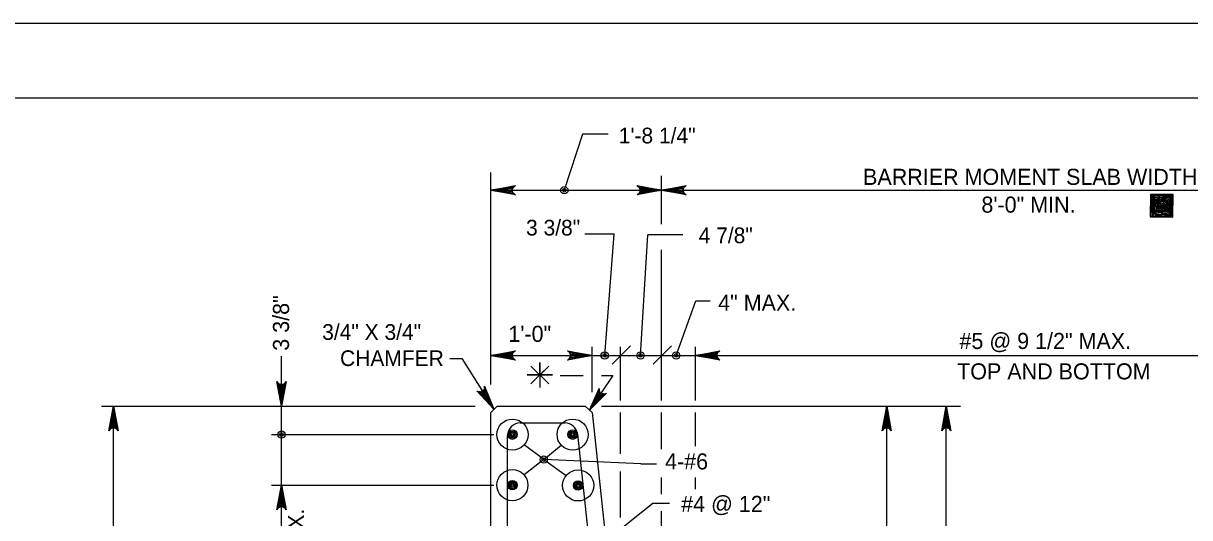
# Model space of a CAD drawing. Extents: x 638167 to 640248, y 296544 to 298920.
# Drawn here: x 639469.7 to 639703.7, y 298821.3 to 298920.5 of the extents above; entities that cross this region are included whole.
import ezdxf

# ---------------------------------------------------------------- set-up
doc = ezdxf.new("R2010")
doc.units = 0
for name, color, linetype in [('1', 7, 'Continuous'), ('50', 7, 'Continuous'), ('57', 7, 'Continuous'), ('PLT-BNDY', 7, 'Continuous')]:
    doc.layers.add(name, color=color, linetype=linetype)

# ---------------------------------------------------------------- blocks, each defined once
blk = doc.blocks.new('DIMDOT')
at = {"layer": '57'}
for radius in [2, 1]:
    blk.add_circle((0, 0), radius, dxfattribs=at)
blk = doc.blocks.new('BAR')
at = {"layer": '50'}
for radius in [2, 1.5, 1, 0.5]:
    blk.add_circle((0, 0), radius, dxfattribs=at)

msp = doc.modelspace()

# ---------------------------------------------------------------- linework, layer by layer
at = {"layer": '1'}
for p, q in [((639832.78, 298905.48), (639046.78, 298905.48)), ((639581.86, 298898.27), (639578.24, 298887)), ((639587.05, 298898.27), (639581.86, 298898.27)), ((639563.48, 298848.05), (639563.48, 298890.55)), ((639597.77, 298880.22), (639597.77, 298889.87)), ((639563.48, 298887), (639760.33, 298887)), ((639698.12, 298883.9), (639698.12, 298883.9)), ((639588.24, 298878.22), (639582.37, 298878.22)), ((639586.34, 298853.88), (639588.24, 298878.22)), ((639593.53, 298853.88), (639595, 298878.06)), ((639602.02, 298878.06), (639595, 298878.06)), ((639597.77, 298844.81), (639597.77, 298875.03)), ((639600.67, 298853.88), (639604.65, 298864.8)), ((639604.65, 298864.8), (639607.48, 298864.8)), ((639583.8, 298846.51), (639583.8, 298855.62)), ((639591.5, 298855.81), (639587.81, 298852.12)), ((639589.51, 298844.81), (639589.51, 298855.62)), ((639599.76, 298855.81), (639596.07, 298852.12)), ((639604.54, 298844.81), (639604.54, 298855.62)), ((639521.48, 298810.67), (639521.48, 298853.73)), ((639555.28, 298853.25), (639557.66, 298853.25)), ((639557.66, 298853.25), (639564.11, 298843.08)), ((639563.48, 298853.88), (639769.86, 298853.88)), ((639573.32, 298849.96), (639573.32, 298849.96)), ((639485.37, 298843.72), (639560.34, 298843.72)), ((639487.76, 298772.6), (639487.76, 298843.72)), ((639563.48, 298842.45), (639564.75, 298843.72)), ((639564.75, 298843.72), (639582.39, 298843.72)), ((639582.39, 298843.72), (639583.8, 298842.45)), ((639585.67, 298843.72), (639657.76, 298843.72)), ((639642.93, 298756.11), (639642.93, 298843.72)), ((639654.9, 298772.6), (639654.9, 298843.72)), ((639563.48, 298777.25), (639563.48, 298842.45)), ((639583.8, 298842.45), (639589.05, 298793.78)), ((639589.51, 298834.18), (639589.51, 298842.45)), ((639597.77, 298835.11), (639597.77, 298842.45)), ((639604.54, 298835.67), (639604.54, 298842.45)), ((639569.4, 298840.33), (639578.34, 298840.33)), ((639580.86, 298838.06), (639586.9, 298782.18)), ((639519.46, 298838), (639564.07, 298838)), ((639566.86, 298796.64), (639566.86, 298837.79)), ((639574.13, 298833), (639570.2, 298835.97)), ((639574.15, 298833.02), (639577.63, 298835.87)), ((639574.13, 298833), (639570.17, 298829.91)), ((639574.13, 298833), (639578.61, 298829.79)), ((639593.58, 298832.17), (639574.15, 298833.02)), ((639593.58, 298832.17), (639596.75, 298832.17)), ((639589.51, 298821.37), (639589.51, 298830.61)), ((639597.77, 298826.08), (639597.77, 298829.41)), ((639604.54, 298827.07), (639604.54, 298829.41)), ((639519.46, 298827.84), (639564.07, 298827.84)), ((639596.1, 298824.28), (639583.45, 298814.15)), ((639596.1, 298824.28), (639599.36, 298824.28)), ((639597.77, 298808.29), (639597.77, 298822.62))]:
    msp.add_line(p, q, dxfattribs=at)
for points in [[(639563.48, 298887), (639568.41, 298887.93), (639568.22, 298887.79), (639568.03, 298887.66), (639567.93, 298887.5), (639567.83, 298887.33), (639567.8, 298887.17), (639567.78, 298887), (639567.8, 298886.84), (639567.83, 298886.67), (639567.93, 298886.51), (639568.03, 298886.34), (639568.22, 298886.21), (639568.41, 298886.08), (639563.48, 298887), (639568.22, 298886.21), (639568.03, 298886.34), (639563.48, 298887), (639567.93, 298886.51), (639567.83, 298886.67), (639563.48, 298887), (639567.8, 298886.84), (639567.78, 298887), (639563.48, 298887), (639567.8, 298887.17), (639567.83, 298887.33), (639563.48, 298887), (639567.93, 298887.5), (639568.03, 298887.66), (639563.48, 298887), (639568.22, 298887.79)], [(639597.77, 298887), (639592.83, 298886.08), (639593.02, 298886.21), (639593.21, 298886.34), (639593.31, 298886.51), (639593.41, 298886.67), (639593.44, 298886.84), (639593.47, 298887), (639593.44, 298887.17), (639593.41, 298887.33), (639593.31, 298887.5), (639593.21, 298887.66), (639593.02, 298887.79), (639592.83, 298887.93), (639597.77, 298887), (639593.02, 298887.79), (639593.21, 298887.66), (639597.77, 298887), (639593.31, 298887.5), (639593.41, 298887.33), (639597.77, 298887), (639593.44, 298887.17), (639593.47, 298887), (639597.77, 298887), (639593.44, 298886.84), (639593.41, 298886.67), (639597.77, 298887), (639593.31, 298886.51), (639593.21, 298886.34), (639597.77, 298887), (639593.02, 298886.21)], [(639597.77, 298887), (639602.7, 298887.93), (639602.51, 298887.79), (639602.32, 298887.66), (639602.22, 298887.5), (639602.12, 298887.33), (639602.09, 298887.17), (639602.07, 298887), (639602.09, 298886.84), (639602.12, 298886.67), (639602.22, 298886.51), (639602.32, 298886.34), (639602.51, 298886.21), (639602.7, 298886.08), (639597.77, 298887), (639602.51, 298886.21), (639602.32, 298886.34), (639597.77, 298887), (639602.22, 298886.51), (639602.12, 298886.67), (639597.77, 298887), (639602.09, 298886.84), (639602.07, 298887), (639597.77, 298887), (639602.09, 298887.17), (639602.12, 298887.33), (639597.77, 298887), (639602.22, 298887.5), (639602.32, 298887.66), (639597.77, 298887), (639602.51, 298887.79)], [(639695.88, 298886.18), (639695.83, 298881.66), (639700.36, 298881.61), (639700.41, 298886.13), (639695.88, 298886.18), (639696.14, 298881.95), (639700.08, 298881.78), (639700.19, 298885.91), (639696.21, 298885.86), (639696.39, 298882.25), (639699.84, 298882.09), (639699.94, 298885.54), (639696.45, 298885.55), (639696.67, 298882.53), (639699.63, 298882.43), (639699.63, 298885.3), (639696.79, 298885.15), (639697.01, 298882.8), (639699.29, 298882.71), (639699.31, 298884.99), (639697.09, 298884.83), (639697.32, 298883.17), (639698.95, 298882.99), (639699.06, 298884.63), (639697.34, 298884.71), (639697.48, 298883.44), (639698.71, 298883.37), (639698.72, 298884.23), (639697.86, 298884.42), (639697.79, 298883.69), (639698.41, 298883.62), (639698.47, 298883.99), (639698.16, 298883.99), (639696.09, 298886.05), (639700.28, 298885.94), (639695.98, 298881.73), (639700.02, 298881.97), (639696.15, 298885.86), (639699.93, 298884.49), (639696.26, 298885.18), (639699.82, 298883.17), (639696.22, 298884.1), (639699.72, 298882.52), (639696.4, 298883.11), (639699.47, 298882.1), (639696.85, 298882.09), (639697.63, 298885.78), (639698.14, 298882.14), (639698.61, 298885.71), (639699.81, 298882), (639700.12, 298885.73), (639698.77, 298882.69), (639696.03, 298885.92), (639696.32, 298882.01), (639696.94, 298885.17), (639699.88, 298885.67), (639696.58, 298885.92)], [(639563.48, 298853.88), (639568.41, 298854.8), (639568.22, 298854.67), (639568.03, 298854.54), (639567.93, 298854.37), (639567.83, 298854.21), (639567.8, 298854.04), (639567.78, 298853.88), (639567.8, 298853.71), (639567.83, 298853.54), (639567.93, 298853.38), (639568.03, 298853.21), (639568.22, 298853.08), (639568.41, 298852.95), (639563.48, 298853.88), (639568.22, 298853.08), (639568.03, 298853.21), (639563.48, 298853.88), (639567.93, 298853.38), (639567.83, 298853.54), (639563.48, 298853.88), (639567.8, 298853.71), (639567.78, 298853.88), (639563.48, 298853.88), (639567.8, 298854.04), (639567.83, 298854.21), (639563.48, 298853.88), (639567.93, 298854.37), (639568.03, 298854.54), (639563.48, 298853.88), (639568.22, 298854.67)], [(639583.8, 298853.88), (639578.86, 298852.95), (639579.05, 298853.08), (639579.24, 298853.21), (639579.34, 298853.38), (639579.44, 298853.54), (639579.47, 298853.71), (639579.5, 298853.88), (639579.47, 298854.04), (639579.44, 298854.21), (639579.34, 298854.37), (639579.24, 298854.54), (639579.05, 298854.67), (639578.86, 298854.8), (639583.8, 298853.88), (639579.05, 298854.67), (639579.24, 298854.54), (639583.8, 298853.88), (639579.34, 298854.37), (639579.44, 298854.21), (639583.8, 298853.88), (639579.47, 298854.04), (639579.5, 298853.88), (639583.8, 298853.88), (639579.47, 298853.71), (639579.44, 298853.54), (639583.8, 298853.88), (639579.34, 298853.38), (639579.24, 298853.21), (639583.8, 298853.88), (639579.05, 298853.08)], [(639604.54, 298853.88), (639609.47, 298854.8), (639609.28, 298854.67), (639609.09, 298854.54), (639608.99, 298854.37), (639608.9, 298854.21), (639608.87, 298854.04), (639608.84, 298853.88), (639608.87, 298853.71), (639608.9, 298853.54), (639608.99, 298853.38), (639609.09, 298853.21), (639609.28, 298853.08), (639609.47, 298852.95), (639604.54, 298853.88), (639609.28, 298853.08), (639609.09, 298853.21), (639604.54, 298853.88), (639608.99, 298853.38), (639608.9, 298853.54), (639604.54, 298853.88), (639608.87, 298853.71), (639608.84, 298853.88), (639604.54, 298853.88), (639608.87, 298854.04), (639608.9, 298854.21), (639604.54, 298853.88), (639608.99, 298854.37), (639609.09, 298854.54), (639604.54, 298853.88), (639609.28, 298854.67)], [(639571.54, 298851.74), (639575.11, 298848.18), (639573.32, 298849.96), (639575.11, 298851.74), (639571.54, 298848.18), (639573.32, 298849.96), (639570.8, 298849.96), (639575.84, 298849.96), (639573.32, 298849.96), (639573.32, 298852.48), (639573.32, 298847.44)], [(639577.39, 298849.88), (639582.01, 298849.88)], [(639585.73, 298849.88), (639588, 298849.88), (639583.3, 298842.9)], [(639521.48, 298843.72), (639520.56, 298848.65), (639520.69, 298848.46), (639520.82, 298848.27), (639520.99, 298848.17), (639521.15, 298848.07), (639521.32, 298848.04), (639521.48, 298848.02), (639521.65, 298848.04), (639521.81, 298848.07), (639521.98, 298848.17), (639522.14, 298848.27), (639522.28, 298848.46), (639522.41, 298848.65), (639521.48, 298843.72), (639522.28, 298848.46), (639522.14, 298848.27), (639521.48, 298843.72), (639521.98, 298848.17), (639521.81, 298848.07), (639521.48, 298843.72), (639521.65, 298848.04), (639521.48, 298848.02), (639521.48, 298843.72), (639521.32, 298848.04), (639521.15, 298848.07), (639521.48, 298843.72), (639520.99, 298848.17), (639520.82, 298848.27), (639521.48, 298843.72), (639520.69, 298848.46)], [(639564.11, 298843.08), (639560.69, 298846.75), (639560.9, 298846.66), (639561.11, 298846.57), (639561.31, 298846.58), (639561.5, 298846.58), (639561.65, 298846.65), (639561.81, 298846.71), (639561.93, 298846.82), (639562.06, 298846.94), (639562.14, 298847.11), (639562.23, 298847.28), (639562.24, 298847.51), (639562.25, 298847.74), (639564.11, 298843.08), (639562.24, 298847.51), (639562.23, 298847.28), (639564.11, 298843.08), (639562.14, 298847.11), (639562.06, 298846.94), (639564.11, 298843.08), (639561.93, 298846.82), (639561.81, 298846.71), (639564.11, 298843.08), (639561.65, 298846.65), (639561.5, 298846.58), (639564.11, 298843.08), (639561.31, 298846.58), (639561.11, 298846.57), (639564.11, 298843.08), (639560.9, 298846.66)], [(639583.3, 298842.9), (639585.21, 298847.28), (639585.21, 298847.06), (639585.21, 298846.84), (639585.29, 298846.68), (639585.37, 298846.51), (639585.48, 298846.4), (639585.6, 298846.29), (639585.74, 298846.22), (639585.89, 298846.16), (639586.07, 298846.15), (639586.26, 298846.13), (639586.46, 298846.21), (639586.67, 298846.29), (639583.3, 298842.9), (639586.46, 298846.21), (639586.26, 298846.13), (639583.3, 298842.9), (639586.07, 298846.15), (639585.89, 298846.16), (639583.3, 298842.9), (639585.74, 298846.22), (639585.6, 298846.29), (639583.3, 298842.9), (639585.48, 298846.4), (639585.37, 298846.51), (639583.3, 298842.9), (639585.29, 298846.68), (639585.21, 298846.84), (639583.3, 298842.9), (639585.21, 298847.06)], [(639487.76, 298843.72), (639488.68, 298838.78), (639488.55, 298838.97), (639488.42, 298839.16), (639488.25, 298839.26), (639488.09, 298839.36), (639487.92, 298839.39), (639487.76, 298839.42), (639487.59, 298839.39), (639487.43, 298839.36), (639487.26, 298839.26), (639487.1, 298839.16), (639486.97, 298838.97), (639486.83, 298838.78), (639487.76, 298843.72), (639486.97, 298838.97), (639487.1, 298839.16), (639487.76, 298843.72), (639487.26, 298839.26), (639487.43, 298839.36), (639487.76, 298843.72), (639487.59, 298839.39), (639487.76, 298839.42), (639487.76, 298843.72), (639487.92, 298839.39), (639488.09, 298839.36), (639487.76, 298843.72), (639488.25, 298839.26), (639488.42, 298839.16), (639487.76, 298843.72), (639488.55, 298838.97)], [(639642.93, 298843.72), (639643.85, 298838.78), (639643.72, 298838.97), (639643.59, 298839.16), (639643.42, 298839.26), (639643.26, 298839.36), (639643.09, 298839.39), (639642.93, 298839.42), (639642.76, 298839.39), (639642.6, 298839.36), (639642.43, 298839.26), (639642.27, 298839.16), (639642.13, 298838.97), (639642, 298838.78), (639642.93, 298843.72), (639642.13, 298838.97), (639642.27, 298839.16), (639642.93, 298843.72), (639642.43, 298839.26), (639642.6, 298839.36), (639642.93, 298843.72), (639642.76, 298839.39), (639642.93, 298839.42), (639642.93, 298843.72), (639643.09, 298839.39), (639643.26, 298839.36), (639642.93, 298843.72), (639643.42, 298839.26), (639643.59, 298839.16), (639642.93, 298843.72), (639643.72, 298838.97)], [(639654.9, 298843.72), (639655.82, 298838.78), (639655.69, 298838.97), (639655.56, 298839.16), (639655.39, 298839.26), (639655.23, 298839.36), (639655.06, 298839.39), (639654.9, 298839.42), (639654.73, 298839.39), (639654.57, 298839.36), (639654.4, 298839.26), (639654.24, 298839.16), (639654.1, 298838.97), (639653.97, 298838.78), (639654.9, 298843.72), (639654.1, 298838.97), (639654.24, 298839.16), (639654.9, 298843.72), (639654.4, 298839.26), (639654.57, 298839.36), (639654.9, 298843.72), (639654.73, 298839.39), (639654.9, 298839.42), (639654.9, 298843.72), (639655.06, 298839.39), (639655.23, 298839.36), (639654.9, 298843.72), (639655.39, 298839.26), (639655.56, 298839.16), (639654.9, 298843.72), (639655.69, 298838.97)], [(639521.48, 298827.84), (639522.41, 298822.91), (639522.28, 298823.1), (639522.14, 298823.29), (639521.98, 298823.38), (639521.81, 298823.48), (639521.65, 298823.51), (639521.48, 298823.54), (639521.32, 298823.51), (639521.15, 298823.48), (639520.99, 298823.38), (639520.82, 298823.29), (639520.69, 298823.1), (639520.56, 298822.91), (639521.48, 298827.84), (639520.69, 298823.1), (639520.82, 298823.29), (639521.48, 298827.84), (639520.99, 298823.38), (639521.15, 298823.48), (639521.48, 298827.84), (639521.32, 298823.51), (639521.48, 298823.54), (639521.48, 298827.84), (639521.65, 298823.51), (639521.81, 298823.48), (639521.48, 298827.84), (639521.98, 298823.38), (639522.14, 298823.29), (639521.48, 298827.84), (639522.28, 298823.1)]]:
    msp.add_lwpolyline(points, dxfattribs=at)
for centre in [(639567.83, 298838), (639579.91, 298838), (639567.82, 298827.87), (639581.01, 298827.81)]:
    msp.add_circle(centre, 3.12, dxfattribs=at)
for centre, start, end in [((639569.4, 298837.79), 90, 180), ((639578.34, 298837.79), 6.1633, 90)]:
    msp.add_arc(centre, 2.54, start, end, dxfattribs=at)
at = {"layer": 'PLT-BNDY'}
msp.add_lwpolyline([(639007.78, 298920.48), (639848.78, 298920.48), (639848.78, 298326.48), (639007.78, 298326.48)], close=True, dxfattribs=at)

# ---------------------------------------------------------------- block references
at = {"layer": '1', "xscale": 0.3674999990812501, "yscale": 0.36749999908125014}
for p in [(639578.24, 298887), (639586.34, 298853.88), (639593.53, 298853.88), (639600.67, 298853.88), (639521.48, 298838), (639574.12, 298832.99)]:
    msp.add_blockref('DIMDOT', p, dxfattribs=at)
at = {"layer": '1', "xscale": 0.4762509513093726, "yscale": 0.4762509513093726, "rotation": -90.00000000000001}
for p in [(639567.83, 298838), (639579.91, 298838), (639567.82, 298827.87), (639581.01, 298827.81)]:
    msp.add_blockref('BAR', p, dxfattribs=at)

# ---------------------------------------------------------------- texts
at = {"layer": '1'}
for s, height, p in [('1\'-8 1/4"', 3.15, (639589.17, 298896.4)), ('BARRIER MOMENT SLAB WIDTH', 3.2256, (639638.19, 298888.08)), ('8\'-0" MIN.', 3.226, (639661.94, 298882.51)), ('3 3/8"', 3.15, (639570.56, 298877.93)), ('4 7/8"', 3.15, (639605.2, 298876.39)), ('4" MAX.', 3.226, (639609.11, 298862.83)), ('3/4" X 3/4"', 3.15, (639529.65, 298857)), ('1\'-0"', 3.226, (639567.01, 298856.6)), ('#5 @ 9 1/2" MAX.', 3.2256, (639657.54, 298855.17)), ('CHAMFER', 3.15, (639533.23, 298851.75)), ('TOP AND BOTTOM', 3.2256, (639657.07, 298849.07)), ('4-#6', 3.226, (639598.45, 298831.01)), ('#4 @ 12"', 3.226, (639601.69, 298822.49))]:
    msp.add_text(s, height=height, dxfattribs=at).set_placement(p)
for s, p in [('3 3/8"', (639522.99, 298854.82)), ('MAX.', (639526.01, 298812.62))]:
    msp.add_text(s, height=3.226, rotation=90, dxfattribs=at).set_placement(p)

doc.saveas('drawing.dxf')
